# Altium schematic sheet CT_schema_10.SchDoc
size 382 x 278 mm
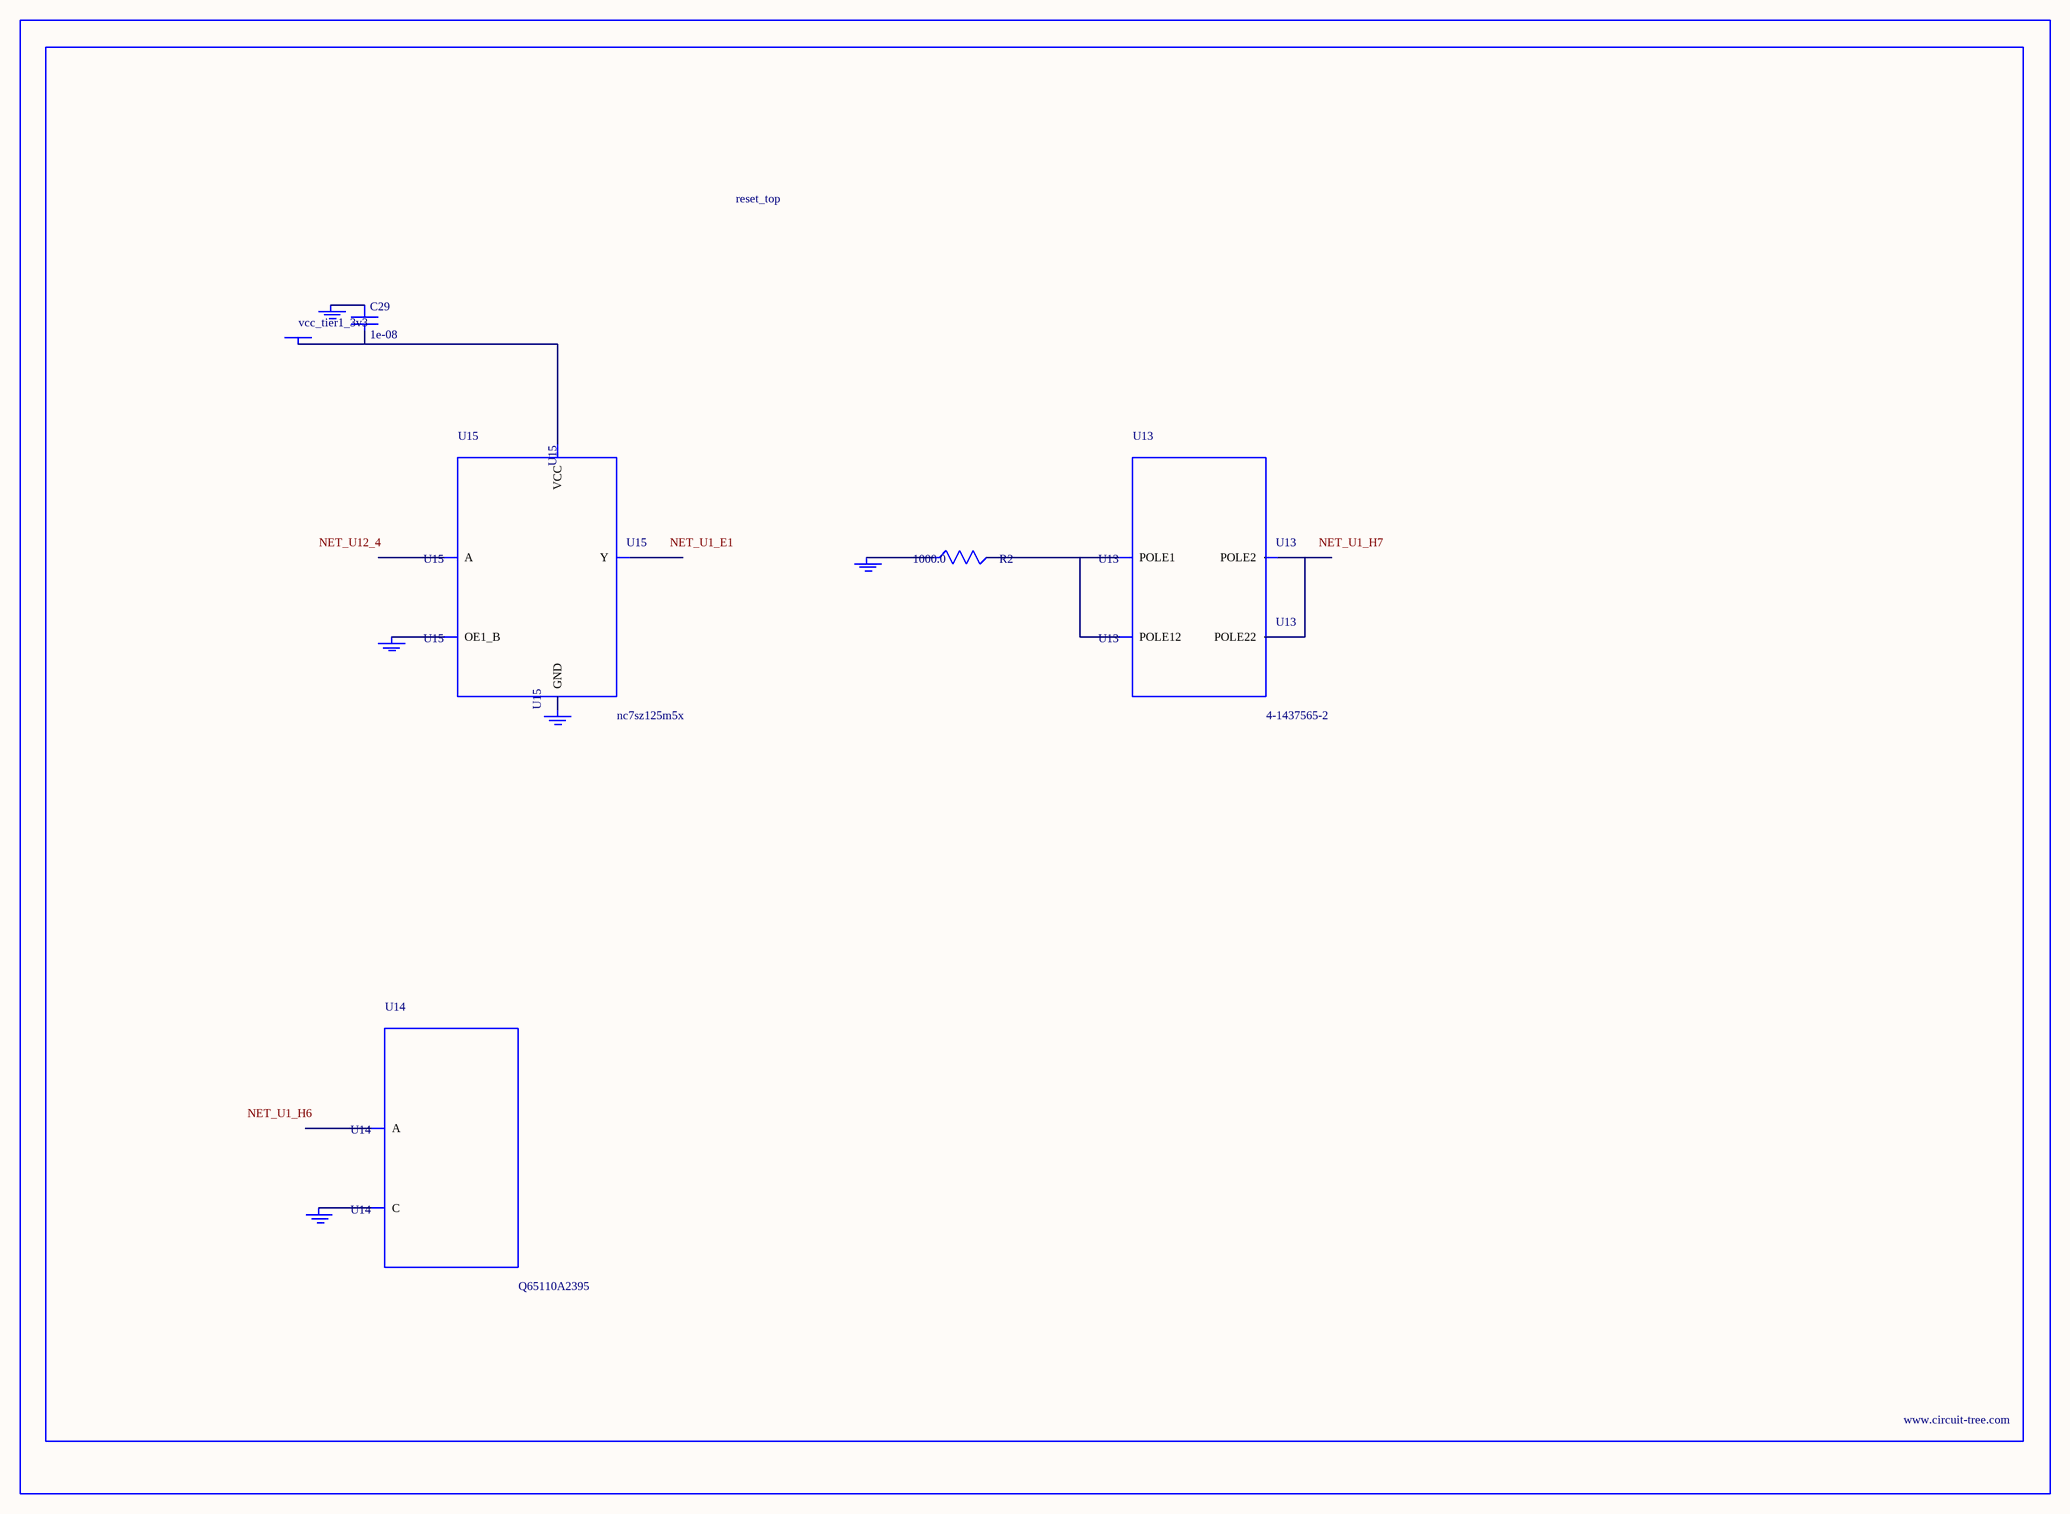
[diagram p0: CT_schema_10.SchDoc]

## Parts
BORDER9  (no value)
C29  1e-08  [C0402]
GND_INSTANCE_9_0  (no value)
GND_INSTANCE_9_1  (no value)
GND_INSTANCE_9_2  (no value)
GND_INSTANCE_9_3  (no value)
GND_INSTANCE_9_4  (no value)
POWER_INSTANCE_9_0  vcc_tier1_3v3
R2  1000.0  [R0603]
U13  4-1437565-2  [SW_4-1437565-2]
U14  Q65110A2395  [LGM67K-G1J2-24-Z]
U15  nc7sz125m5x  [NC7SZ125M5X]

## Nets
NetC29_1: C29.1 GND_INSTANCE_9_2.0(GND)
NetC29_2: C29.2 POWER_INSTANCE_9_0.0(PWR) U15.5(VCC)
NetGND_INSTANCE_9_0_0: GND_INSTANCE_9_0.0(GND) R2.1
NetGND_INSTANCE_9_1_0: GND_INSTANCE_9_1.0(GND) U14.C
NetGND_INSTANCE_9_3_0: GND_INSTANCE_9_3.0(GND) U15.1(OE1_B)
NetGND_INSTANCE_9_4_0: GND_INSTANCE_9_4.0(GND) U15.3(GND)
NetR2_2: R2.2 U13.1(POLE1) U13.2(POLE12)
NetU13_3: U13.3(POLE2) U13.4(POLE22)

Not connected (* = marked no-connect by the designer): U14 A; U15 2(A) 4(Y)

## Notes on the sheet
- Labels drawn without touching a wire or pin: NET_U1_E1, NET_U1_H6, NET_U1_H7, NET_U12_4

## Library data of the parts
BORDER9 = BORDER_PAGE9
C29 = C0402C103K3RAC
GND_INSTANCE_9_0-GND_INSTANCE_9_4 = GND
POWER_INSTANCE_9_0 = PWR
R2 = RC0603JR-071KL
